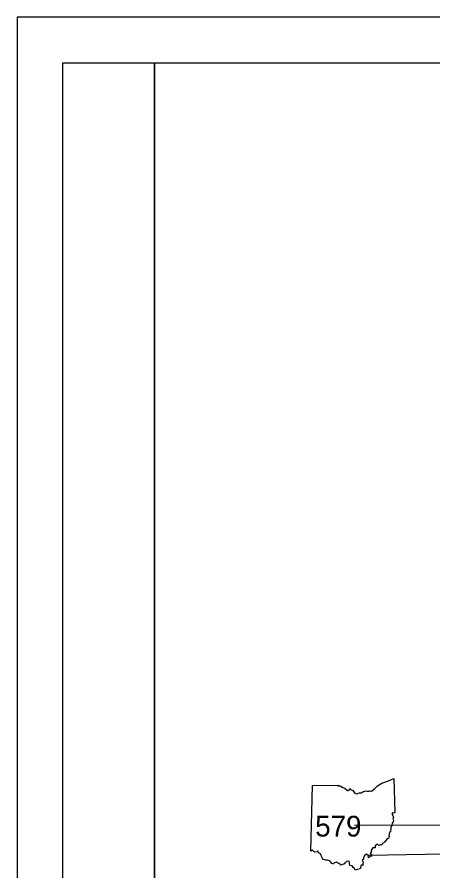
# Model space of a CAD drawing. Extents: x -82 to 873, y 0 to 440.
# Drawn here: x 0 to 90.7, y 253.6 to 440 of the extents above; entities that cross this region are included whole.
import ezdxf

# ---------------------------------------------------------------- set-up
doc = ezdxf.new("R2010")
doc.units = 0
for name, color, linetype in [('DV_X_County_Line', 7, 'Continuous'), ('GM_X_Interstate_Route', 7, 'Continuous'), ('PV_P_Text', 7, 'Continuous'), ('SH_Border', 7, 'Continuous'), ('SH_Cut_Line', 7, 'Continuous')]:
    doc.layers.add(name, color=color, linetype=linetype)

msp = doc.modelspace()

# ---------------------------------------------------------------- linework, layer by layer
at = {"layer": 'DV_X_County_Line'}
msp.add_lwpolyline([(73.63, 263.62), (99.78, 263.72)], dxfattribs=at)
at = {"layer": 'GM_X_Interstate_Route'}
msp.add_lwpolyline([(76.67, 257.1), (93.16, 257.37)], dxfattribs=at)
at = {"layer": 'PV_P_Text'}
msp.add_line((64.06, 257.94), (64.46, 272.31), dxfattribs=at)
msp.add_line((64.06, 257.94), (64.46, 272.31), dxfattribs=at)
for points in [[(64.46, 272.31), (70.03, 272.4), (69.95, 272.23), (70.47, 272.19), (71.03, 271.88), (71.5, 271.69), (72.08, 271.23), (72.43, 271.24), (72.57, 271.61), (72.84, 271.32), (73.15, 271.27), (73.7, 270.59), (74.14, 270.44), (74.68, 270.67), (75.08, 270.71), (75.38, 270.94), (76.14, 271.14), (76.35, 271.02), (76.76, 271.05), (76.96, 271.14), (77.32, 271.06), (77.94, 271.58), (78.58, 272.2), (79.56, 272.78), (81.03, 273.33), (82.19, 273.82), (82.36, 266.37)], [(64.46, 272.31), (70.03, 272.4), (69.95, 272.23), (70.47, 272.19), (71.03, 271.88), (71.5, 271.69), (72.08, 271.23), (72.43, 271.24), (72.57, 271.61), (72.84, 271.32), (73.15, 271.27), (73.7, 270.59), (74.14, 270.44), (74.68, 270.67), (75.08, 270.71), (75.38, 270.94), (76.14, 271.14), (76.35, 271.02), (76.76, 271.05), (76.96, 271.14), (77.32, 271.06), (77.94, 271.58), (78.58, 272.2), (79.56, 272.78), (81.03, 273.33), (82.19, 273.82), (82.36, 266.37)], [(82.36, 266.37), (82.19, 266.26), (81.92, 266.31), (81.74, 266.1), (81.97, 265.75), (82.07, 265.38), (81.98, 264.98), (82.07, 264.64), (82.01, 264.36), (81.84, 264.08), (81.78, 263.82), (81.64, 263.54), (81.65, 263.38), (81.51, 263.26), (81.54, 262.79), (81.47, 262.53), (81.49, 262.31), (81.27, 262.25), (81.32, 262.07), (81.18, 261.92), (81.21, 261.68), (81.05, 261.52), (81.21, 261.21), (81.09, 261.11), (80.98, 260.73), (80.7, 260.65), (80.13, 259.96), (79.93, 259.7), (79.71, 259.63), (79.58, 259.36), (79.31, 259.36), (78.89, 259.17), (78.62, 259.49), (78.14, 259.11), (78.09, 258.66), (77.49, 258.67), (77.51, 258.45), (77.38, 258.38), (77.26, 258.15), (77.33, 257.75), (77.05, 257.65), (77.08, 257.41), (77.26, 257.27), (77.34, 256.82), (77.04, 256.91), (76.8, 256.54), (76.55, 256.62), (76.63, 256.94), (76.21, 257.33), (75.8, 257.02), (75.59, 256.53), (75.59, 256.2), (75.29, 256), (75.49, 255.53), (75.45, 255.21), (75.46, 254.9), (75.08, 254.92), (74.86, 254.09)], [(82.36, 266.37), (82.19, 266.26), (81.92, 266.31), (81.74, 266.1), (81.97, 265.75), (82.07, 265.38), (81.98, 264.98), (82.07, 264.64), (82.01, 264.36), (81.84, 264.08), (81.78, 263.82), (81.64, 263.54), (81.65, 263.38), (81.51, 263.26), (81.54, 262.79), (81.47, 262.53), (81.49, 262.31), (81.27, 262.25), (81.32, 262.07), (81.18, 261.92), (81.21, 261.68), (81.05, 261.52), (81.21, 261.21), (81.09, 261.11), (80.98, 260.73), (80.7, 260.65), (80.13, 259.96), (79.93, 259.7), (79.71, 259.63), (79.58, 259.36), (79.31, 259.36), (78.89, 259.17), (78.62, 259.49), (78.14, 259.11), (78.09, 258.66), (77.49, 258.67), (77.51, 258.45), (77.38, 258.38), (77.26, 258.15), (77.33, 257.75), (77.05, 257.65), (77.08, 257.41), (77.26, 257.27), (77.34, 256.82), (77.04, 256.91), (76.8, 256.54), (76.55, 256.62), (76.63, 256.94), (76.21, 257.33), (75.8, 257.02), (75.59, 256.53), (75.59, 256.2), (75.29, 256), (75.49, 255.53), (75.45, 255.21), (75.46, 254.9), (75.08, 254.92), (74.86, 254.09)], [(74.86, 254.09), (74.2, 253.93), (73.75, 253.84), (73.59, 254.21), (73.27, 254.41), (73.06, 254.79), (72.6, 254.84), (72.49, 255.36), (72.44, 255.78), (71.8, 255.67), (71.63, 255.42), (71.4, 255.35), (71.27, 255.09), (70.97, 255.07), (70.64, 254.94), (70.42, 255.2), (69.88, 255.45), (69.64, 255.58), (69.14, 255.38), (69.03, 255.14), (68.62, 255.25), (68.53, 255.51), (68.29, 255.6), (68.23, 255.88), (67.71, 256.03), (67.31, 255.97), (66.61, 256.2), (66.57, 256.58), (66.33, 257.04), (66.2, 257.36), (65.76, 257.6), (65.67, 257.98), (65.52, 257.97), (65.39, 257.81), (64.9, 257.74), (64.7, 257.9), (64.43, 258.16), (64.06, 257.94)], [(74.86, 254.09), (74.2, 253.93), (73.75, 253.84), (73.59, 254.21), (73.27, 254.41), (73.06, 254.79), (72.6, 254.84), (72.49, 255.36), (72.44, 255.78), (71.8, 255.67), (71.63, 255.42), (71.4, 255.35), (71.27, 255.09), (70.97, 255.07), (70.64, 254.94), (70.42, 255.2), (69.88, 255.45), (69.64, 255.58), (69.14, 255.38), (69.03, 255.14), (68.62, 255.25), (68.53, 255.51), (68.29, 255.6), (68.23, 255.88), (67.71, 256.03), (67.31, 255.97), (66.61, 256.2), (66.57, 256.58), (66.33, 257.04), (66.2, 257.36), (65.76, 257.6), (65.67, 257.98), (65.52, 257.97), (65.39, 257.81), (64.9, 257.74), (64.7, 257.9), (64.43, 258.16), (64.06, 257.94)]]:
    msp.add_lwpolyline(points, dxfattribs=at)
at = {"layer": 'SH_Border'}
for points in [[(10, 430), (30, 430), (30, 10), (10, 10)], [(30, 430), (670, 430), (670, 10), (30, 10)]]:
    msp.add_lwpolyline(points, close=True, dxfattribs=at)
at = {"layer": 'SH_Cut_Line'}
msp.add_lwpolyline([(0, 0), (680, 0), (680, 440), (0, 440)], close=True, dxfattribs=at)

# ---------------------------------------------------------------- texts
at = {"layer": 'PV_P_Text'}
msp.add_text('579', height=4.528, rotation=0.005, dxfattribs=at).set_placement((65.02, 261.15))

doc.saveas('drawing.dxf')
